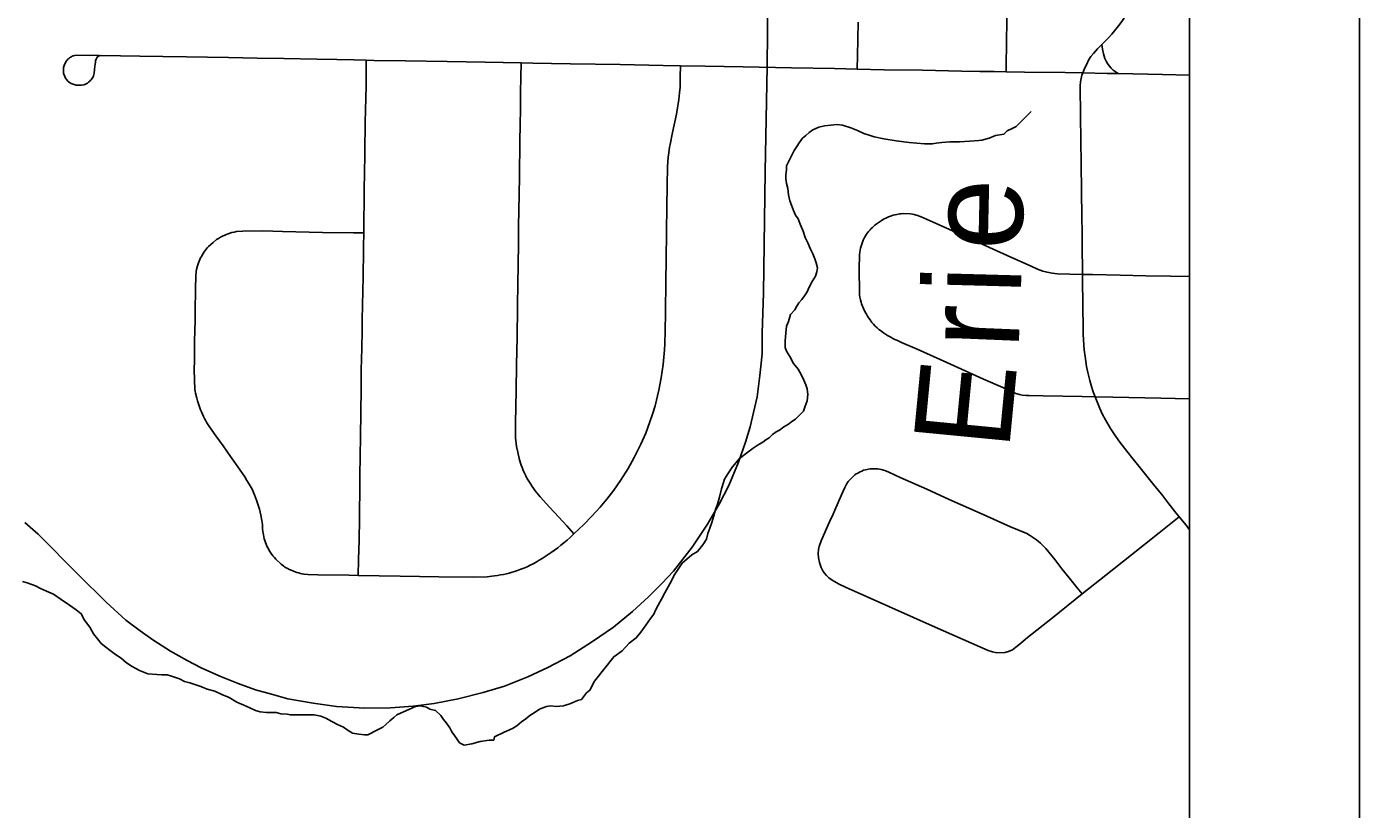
# Model space of a CAD drawing. Extents: x 0 to 34, y 0 to 22.
# Drawn here: x 8.215 to 9, y 16.402 to 16.863 of the extents above; entities that cross this region are included whole.
import ezdxf

# ---------------------------------------------------------------- set-up
doc = ezdxf.new("R2010")
doc.units = 0
for name, color, linetype in [('GM_X_City_Street', 7, 'Continuous'), ('GM_X_County_Text', 7, 'Continuous'), ('GM_X_Minor_River', 7, 'Continuous'), ('GM_X_Rail_Line', 7, 'Continuous'), ('GM_X_Rail_Line_Text', 7, 'Continuous'), ('SH_Cut_Line', 7, 'Continuous'), ('SH_Data', 7, 'Continuous')]:
    doc.layers.add(name, color=color, linetype=linetype)

msp = doc.modelspace()

# ---------------------------------------------------------------- linework, layer by layer
at = {"layer": 'GM_X_City_Street'}
for points in [[(8.8371, 16.83566), (8.83838, 16.83864), (8.8394, 16.84088), (8.84045, 16.84306), (8.84194, 16.84532), (8.84336, 16.84714), (8.84579, 16.8498), (8.84834, 16.85231), (8.85039, 16.85424), (8.85233, 16.85629), (8.85415, 16.85844), (8.85737, 16.86239), (8.85892, 16.86442), (8.86043, 16.86647), (8.86914, 16.8802), (8.87274, 16.88638), (8.87747, 16.8944), (8.88206, 16.90192), (8.88668, 16.90932), (8.89644, 16.92543), (8.9, 16.93126)], [(8.70428, 16.83786), (8.70443, 16.84591), (8.70458, 16.8554), (8.70485, 16.86555)], [(8.79191, 16.83632), (8.79203, 16.84148), (8.7921, 16.85181), (8.79247, 16.86816)], [(8.25768, 16.84593), (8.24458, 16.84607), (8.24336, 16.84591), (8.24256, 16.84568), (8.24196, 16.84548), (8.24141, 16.84519), (8.24087, 16.84487), (8.24036, 16.8445), (8.23987, 16.8441), (8.23941, 16.84367), (8.23899, 16.84322), (8.23859, 16.84272), (8.23823, 16.84221), (8.2379, 16.84167), (8.23737, 16.84059), (8.237, 16.83948), (8.23686, 16.83891), (8.23677, 16.83833), (8.2367, 16.83717), (8.23685, 16.83542), (8.23697, 16.83485), (8.23746, 16.83349), (8.23792, 16.83259), (8.23849, 16.83171), (8.23925, 16.83083), (8.23974, 16.83043), (8.24078, 16.82973), (8.24133, 16.82943), (8.2419, 16.82917), (8.24308, 16.82874), (8.24369, 16.82859), (8.2443, 16.82847), (8.24493, 16.82839), (8.24743, 16.82846), (8.24866, 16.82872), (8.24926, 16.82891), (8.25042, 16.8294), (8.25097, 16.82969), (8.25152, 16.83012), (8.25204, 16.83059), (8.25253, 16.83109), (8.25299, 16.83162), (8.25341, 16.83217), (8.2538, 16.83276), (8.25416, 16.83336), (8.25441, 16.83398), (8.25462, 16.83478), (8.25479, 16.83558), (8.25504, 16.83766), (8.25528, 16.83956), (8.25538, 16.84087), (8.25554, 16.84183), (8.25571, 16.84276), (8.25603, 16.8437), (8.25637, 16.84442), (8.25669, 16.84491), (8.25715, 16.84536), (8.25783, 16.84568), (8.25888, 16.84593), (8.28165, 16.84558), (8.29524, 16.84527), (8.3092, 16.84518), (8.33395, 16.84463), (8.35092, 16.84431), (8.36661, 16.8441), (8.38596, 16.84373), (8.39783, 16.84351), (8.40795, 16.84325), (8.41512, 16.84312), (8.41962, 16.84301), (8.43815, 16.84271), (8.46281, 16.84228), (8.48513, 16.8419), (8.50624, 16.84159), (8.51312, 16.84143), (8.52411, 16.84125), (8.53541, 16.84103), (8.56461, 16.8405), (8.58992, 16.84004), (8.60026, 16.83986), (8.61476, 16.83959), (8.63711, 16.83921), (8.66549, 16.83872), (8.69095, 16.83818), (8.70428, 16.83786), (8.72013, 16.83755), (8.74273, 16.8372), (8.76561, 16.83676), (8.77657, 16.83657), (8.78489, 16.83644), (8.79191, 16.83632), (8.80283, 16.83612), (8.82669, 16.83582), (8.8371, 16.83566), (8.85151, 16.83539), (8.85798, 16.83526), (8.88413, 16.83471), (8.9, 16.83441)], [(8.85798, 16.83526), (8.85505, 16.83735), (8.85379, 16.83851), (8.85264, 16.83975), (8.85164, 16.84113), (8.85079, 16.8426), (8.85011, 16.84415), (8.8497, 16.84548), (8.84934, 16.84683), (8.84876, 16.84955), (8.84834, 16.85231)], [(8.41364, 16.7415), (8.40752, 16.74157), (8.38922, 16.7418), (8.36581, 16.74231), (8.36, 16.74245), (8.3542, 16.74262), (8.34241, 16.74253), (8.33875, 16.74227), (8.33729, 16.74196), (8.33591, 16.74166), (8.33322, 16.74082), (8.33182, 16.74024), (8.33034, 16.73953), (8.32933, 16.73905), (8.32808, 16.73824), (8.32698, 16.73753), (8.32483, 16.73579), (8.32358, 16.73475), (8.32217, 16.73339), (8.32146, 16.73265), (8.32078, 16.73188), (8.32015, 16.73108), (8.31954, 16.73026), (8.31899, 16.7294), (8.31796, 16.72764), (8.31749, 16.72674), (8.31707, 16.72583), (8.3163, 16.72395), (8.31568, 16.72202), (8.31518, 16.72002), (8.31498, 16.71898), (8.31483, 16.71794), (8.31472, 16.7169), (8.31465, 16.71585), (8.31453, 16.70892), (8.31433, 16.69476), (8.31424, 16.69148), (8.31407, 16.68226), (8.314, 16.6796), (8.31383, 16.66521), (8.31376, 16.66237), (8.31388, 16.65388), (8.31404, 16.6505), (8.31418, 16.64939), (8.31435, 16.64827), (8.31458, 16.64707), (8.31524, 16.64431), (8.31571, 16.64258), (8.31623, 16.64085), (8.3168, 16.63914), (8.31742, 16.63745), (8.31797, 16.63611), (8.31855, 16.63479), (8.31918, 16.63348), (8.31984, 16.6322), (8.32053, 16.63093), (8.32127, 16.62969), (8.32204, 16.62846), (8.32284, 16.62726), (8.32648, 16.62213), (8.33079, 16.61609), (8.33517, 16.60995), (8.33798, 16.60582), (8.33941, 16.60386), (8.34081, 16.60187), (8.34218, 16.59986), (8.3435, 16.59783), (8.3448, 16.59577), (8.34605, 16.5937), (8.34728, 16.5916), (8.348, 16.59018), (8.34868, 16.58873), (8.34932, 16.58727), (8.34992, 16.58579), (8.35054, 16.5841), (8.35113, 16.58238), (8.35166, 16.58065), (8.35216, 16.57891), (8.3526, 16.57715), (8.353, 16.57539), (8.35358, 16.57229), (8.35377, 16.57096), (8.3539, 16.56962), (8.35405, 16.56713), (8.35416, 16.56599), (8.3543, 16.56485), (8.35449, 16.56372), (8.35471, 16.56259), (8.35498, 16.56147), (8.35528, 16.56037), (8.35568, 16.55928), (8.35611, 16.55821), (8.35658, 16.55714), (8.3571, 16.5561), (8.35766, 16.55509), (8.35798, 16.55448), (8.35832, 16.55389), (8.35869, 16.55332), (8.35909, 16.55276), (8.36013, 16.55141), (8.36096, 16.55044), (8.36182, 16.54951), (8.36271, 16.54861), (8.3643, 16.54709), (8.36499, 16.54647), (8.36571, 16.54589), (8.36645, 16.54534), (8.36721, 16.54482), (8.368, 16.54434), (8.36881, 16.5439), (8.36963, 16.54348), (8.37047, 16.54311), (8.37231, 16.54237), (8.37329, 16.542), (8.37429, 16.54167), (8.37531, 16.54137), (8.37633, 16.54112), (8.37725, 16.54082), (8.37851, 16.54059), (8.38066, 16.5405), (8.38647, 16.5403), (8.40492, 16.54001), (8.41035, 16.53993), (8.43502, 16.53953), (8.45787, 16.5391), (8.4785, 16.53884), (8.48625, 16.53914), (8.48768, 16.53926), (8.48911, 16.53942), (8.49054, 16.53963), (8.49231, 16.53987), (8.49408, 16.54016), (8.49585, 16.5405), (8.4976, 16.54088), (8.49934, 16.5413), (8.50108, 16.54176), (8.50239, 16.54215), (8.50426, 16.54281), (8.50612, 16.54352), (8.50796, 16.54427), (8.50978, 16.54505), (8.51159, 16.54587), (8.51338, 16.54673), (8.5152, 16.54774), (8.51699, 16.54879), (8.51876, 16.54987), (8.52051, 16.55098), (8.52224, 16.55213), (8.52406, 16.55341), (8.52597, 16.5548), (8.52785, 16.55622), (8.5297, 16.55768), (8.53153, 16.55917), (8.53333, 16.5607), (8.5351, 16.56226), (8.53735, 16.56435), (8.54318, 16.56987), (8.54797, 16.57477), (8.55277, 16.57999), (8.55686, 16.58485), (8.56085, 16.59006), (8.56482, 16.59569), (8.56934, 16.60289), (8.57282, 16.60926), (8.57677, 16.61714), (8.57968, 16.62364), (8.58219, 16.6303), (8.58363, 16.63481), (8.58516, 16.63978), (8.58749, 16.64886), (8.5888, 16.6561), (8.58991, 16.66411), (8.59068, 16.67274), (8.59087, 16.67612), (8.59109, 16.68405), (8.59127, 16.69423), (8.5915, 16.71347), (8.59164, 16.72497), (8.59199, 16.7427), (8.59213, 16.75642), (8.59234, 16.76956), (8.59246, 16.7802), (8.5927, 16.78356), (8.59295, 16.78607), (8.59325, 16.78858), (8.59374, 16.79191), (8.59403, 16.79357), (8.5954, 16.80054), (8.59775, 16.81143), (8.5992, 16.82008), (8.59966, 16.82387), (8.59989, 16.8272), (8.59999, 16.83327), (8.60026, 16.83986)], [(8.41035, 16.53993), (8.41056, 16.54932), (8.41082, 16.56075), (8.41103, 16.57337), (8.41115, 16.58028), (8.41122, 16.58718), (8.4114, 16.59869), (8.41169, 16.62145), (8.41205, 16.6499), (8.41218, 16.66097), (8.41243, 16.67341), (8.41263, 16.68413), (8.41274, 16.69248), (8.41284, 16.69673), (8.41294, 16.70096), (8.41302, 16.70521), (8.4131, 16.70945), (8.41319, 16.71369), (8.41351, 16.73329), (8.41364, 16.7415), (8.41373, 16.7471), (8.41383, 16.76196), (8.41395, 16.76863), (8.4141, 16.77531), (8.41424, 16.78907), (8.41443, 16.8066), (8.41465, 16.81372), (8.41484, 16.82084), (8.41499, 16.82795), (8.41506, 16.83552), (8.41512, 16.84312)], [(8.53735, 16.56435), (8.5333, 16.56902), (8.5286, 16.57416), (8.52303, 16.58003), (8.51761, 16.58606), (8.51657, 16.58724), (8.51558, 16.58843), (8.51462, 16.58967), (8.5137, 16.59093), (8.51282, 16.59222), (8.51198, 16.59354), (8.51118, 16.59487), (8.51045, 16.59603), (8.50975, 16.59722), (8.50909, 16.59843), (8.50847, 16.59965), (8.50789, 16.60089), (8.50734, 16.60215), (8.50683, 16.60343), (8.50636, 16.60472), (8.50593, 16.60603), (8.50555, 16.60734), (8.50519, 16.60867), (8.50427, 16.61244), (8.50356, 16.61581), (8.50335, 16.61748), (8.50318, 16.61915), (8.50305, 16.62083), (8.50297, 16.6225), (8.50308, 16.63095), (8.50318, 16.6377), (8.50353, 16.66238), (8.50381, 16.67318), (8.50389, 16.67858), (8.50415, 16.6992), (8.50433, 16.7109), (8.50469, 16.73485), (8.50484, 16.74541), (8.50512, 16.76399), (8.50528, 16.77493), (8.50559, 16.79545), (8.50576, 16.80499), (8.5059, 16.81453), (8.50602, 16.82407), (8.50617, 16.83306), (8.50624, 16.84159)], [(8.9, 16.56679), (8.89791, 16.5694), (8.89378, 16.57441), (8.89136, 16.57759), (8.88716, 16.58287), (8.88358, 16.58746), (8.87945, 16.59248), (8.87484, 16.59836), (8.87013, 16.60416), (8.86682, 16.60835), (8.86297, 16.61306), (8.85897, 16.6183), (8.8565, 16.62167), (8.85351, 16.62637), (8.85051, 16.63138), (8.84879, 16.6347), (8.84707, 16.63823), (8.84437, 16.64499), (8.8432, 16.64801), (8.84223, 16.65101), (8.84122, 16.6546), (8.84004, 16.65938), (8.8393, 16.66291), (8.83845, 16.66868), (8.83794, 16.67274), (8.83764, 16.67559), (8.83737, 16.68165), (8.83711, 16.7022), (8.83703, 16.71078), (8.83698, 16.71708), (8.83672, 16.73517), (8.83666, 16.74183), (8.83649, 16.75047), (8.8361, 16.78208), (8.83598, 16.79586), (8.83584, 16.81043), (8.83564, 16.82808), (8.83578, 16.83038), (8.8361, 16.83233), (8.83656, 16.83427), (8.8371, 16.83566)], [(8.70544, 16.72015), (8.70556, 16.72851), (8.70573, 16.73013), (8.70593, 16.73134), (8.70619, 16.73255), (8.70652, 16.73375), (8.70689, 16.73493), (8.70732, 16.73608), (8.70781, 16.73722), (8.70855, 16.73869), (8.70916, 16.73976), (8.70981, 16.74079), (8.71038, 16.74158), (8.71098, 16.74236), (8.71184, 16.74335), (8.71252, 16.74406), (8.71322, 16.74475), (8.71396, 16.7454), (8.71472, 16.74602), (8.71551, 16.74661), (8.71659, 16.74734), (8.71828, 16.74849), (8.71918, 16.7491), (8.72011, 16.74967), (8.72107, 16.75018), (8.72273, 16.75095), (8.72444, 16.75157), (8.72549, 16.75187), (8.72654, 16.75212), (8.72926, 16.75261), (8.73015, 16.75272), (8.73149, 16.75282), (8.73554, 16.75268), (8.73688, 16.75247), (8.73776, 16.75229), (8.73907, 16.75195), (8.73992, 16.75169), (8.74077, 16.7514), (8.742, 16.75089), (8.75253, 16.74618), (8.77178, 16.73751), (8.79467, 16.72719), (8.80664, 16.7219), (8.81047, 16.72013), (8.81363, 16.71902), (8.81609, 16.71834), (8.81907, 16.71775), (8.82226, 16.71746), (8.82943, 16.71728), (8.83698, 16.71708), (8.84287, 16.717), (8.85909, 16.71666), (8.87426, 16.71628), (8.88882, 16.71609), (8.9, 16.71581)], [(8.70544, 16.72015), (8.70551, 16.70651), (8.70565, 16.70505), (8.70586, 16.70359), (8.70615, 16.70215), (8.70653, 16.70072), (8.70687, 16.69967), (8.70739, 16.69829), (8.70797, 16.69695), (8.70903, 16.69478), (8.70966, 16.6936), (8.71033, 16.69245), (8.71105, 16.69133), (8.71182, 16.69023), (8.71292, 16.68882), (8.71379, 16.68781), (8.7147, 16.68683), (8.71597, 16.6856), (8.71697, 16.68472), (8.71789, 16.684), (8.71981, 16.68259), (8.72092, 16.68185), (8.72206, 16.68114), (8.72399, 16.68003), (8.72518, 16.67941), (8.72638, 16.67883), (8.7276, 16.67828), (8.73034, 16.67707), (8.73951, 16.67303), (8.75696, 16.66516), (8.77873, 16.65547), (8.78999, 16.65045), (8.7976, 16.64702), (8.79976, 16.64632), (8.80147, 16.64605), (8.80375, 16.64577), (8.80559, 16.6457), (8.81376, 16.64559), (8.83671, 16.64513), (8.84437, 16.64499)], [(8.84437, 16.64499), (8.85485, 16.64486), (8.88306, 16.64428), (8.9, 16.64391)], [(8.83674, 16.52898), (8.83387, 16.53256), (8.82914, 16.53844), (8.82483, 16.54388), (8.82061, 16.54922), (8.81888, 16.55138), (8.81533, 16.55578), (8.81217, 16.55889), (8.80984, 16.56086), (8.8081, 16.56209), (8.80579, 16.56363), (8.80414, 16.56449), (8.79463, 16.56859), (8.77663, 16.57664), (8.75841, 16.58468), (8.74519, 16.59063), (8.72947, 16.59762), (8.7228, 16.60062), (8.72055, 16.60156), (8.71834, 16.60222), (8.71633, 16.60261), (8.71398, 16.60271), (8.7118, 16.60261), (8.70914, 16.60212), (8.70803, 16.60178), (8.70734, 16.60152), (8.70552, 16.60066), (8.70458, 16.60014), (8.70371, 16.59963), (8.70285, 16.59902), (8.70194, 16.59822), (8.70021, 16.59656), (8.69901, 16.59512), (8.698, 16.59356), (8.69696, 16.59173), (8.69605, 16.58946), (8.69501, 16.58725), (8.69101, 16.57833), (8.69002, 16.57598), (8.68797, 16.57153), (8.68297, 16.56026), (8.68176, 16.55691), (8.6814, 16.55512), (8.68121, 16.55287), (8.6814, 16.55021), (8.68199, 16.54747), (8.68305, 16.54463), (8.68403, 16.54261), (8.68484, 16.54145), (8.68623, 16.53989), (8.68751, 16.5385), (8.68942, 16.53705), (8.69324, 16.53492), (8.69775, 16.53289), (8.71019, 16.52739), (8.75023, 16.50951), (8.78142, 16.49563), (8.7839, 16.49493), (8.78639, 16.49442), (8.79125, 16.49459), (8.79344, 16.49522), (8.79571, 16.4962), (8.79767, 16.49765), (8.79947, 16.49898), (8.80462, 16.50344), (8.81919, 16.5149), (8.83674, 16.52898), (8.85062, 16.53999), (8.86587, 16.55207), (8.88203, 16.56501), (8.89378, 16.57441)]]:
    msp.add_lwpolyline(points, dxfattribs=at)
at = {"layer": 'GM_X_County_Text'}
msp.add_lwpolyline([(6.61711, 15.32914), (8.9, 15.30473), (8.9, 20.9), (2.1, 20.9)], dxfattribs=at)
at = {"layer": 'GM_X_Minor_River'}
for points in [[(8.64592, 16.61674), (8.64858, 16.61826), (8.65048, 16.61978), (8.65238, 16.62092), (8.65428, 16.62282), (8.65656, 16.62434), (8.65846, 16.62548), (8.66112, 16.62738), (8.66378, 16.6289), (8.66568, 16.63042), (8.66796, 16.63194), (8.67252, 16.63651), (8.67365, 16.63955), (8.67479, 16.64259), (8.67517, 16.64639), (8.67479, 16.64981), (8.67403, 16.65209), (8.67289, 16.65475), (8.67137, 16.65779), (8.66946, 16.66121), (8.6668, 16.66462), (8.66452, 16.6688), (8.66262, 16.67184), (8.66185, 16.67412), (8.66185, 16.67792), (8.66223, 16.68248), (8.66261, 16.68666), (8.66375, 16.68932), (8.66489, 16.6935), (8.66755, 16.69616), (8.66869, 16.69844), (8.66983, 16.70034), (8.67173, 16.70225), (8.67325, 16.70453), (8.67477, 16.70681), (8.6759, 16.70947), (8.6778, 16.71289), (8.6797, 16.71593), (8.68046, 16.71859), (8.68084, 16.72087), (8.68008, 16.72391), (8.67932, 16.72619), (8.67818, 16.72923), (8.67665, 16.73189), (8.67513, 16.73568), (8.67361, 16.73873), (8.67247, 16.74252), (8.67057, 16.7467), (8.66942, 16.74974), (8.6679, 16.75202), (8.66676, 16.75468), (8.66562, 16.75772), (8.66448, 16.76038), (8.66372, 16.7638), (8.66333, 16.7676), (8.66257, 16.77064), (8.66219, 16.7733), (8.66219, 16.77558), (8.66257, 16.77862), (8.66257, 16.7809), (8.66713, 16.79002), (8.66864, 16.7923), (8.67016, 16.79458), (8.67206, 16.79724), (8.67396, 16.79876), (8.67586, 16.80066), (8.67814, 16.80218), (8.68156, 16.80371), (8.68498, 16.80447), (8.68878, 16.80485), (8.69221, 16.80523), (8.69563, 16.80486), (8.70057, 16.80334), (8.70437, 16.80182), (8.70817, 16.79992), (8.71197, 16.79878), (8.71425, 16.79802), (8.71995, 16.79689), (8.72718, 16.79575), (8.73478, 16.79461), (8.7439, 16.79386), (8.74846, 16.79386), (8.75074, 16.79424), (8.75416, 16.79462), (8.75872, 16.795), (8.76443, 16.79501), (8.77051, 16.79539), (8.77583, 16.79577), (8.77773, 16.79615), (8.78191, 16.79729), (8.78571, 16.79882), (8.79065, 16.79958), (8.79255, 16.80148), (8.79559, 16.803), (8.79787, 16.80414), (8.80053, 16.8068), (8.80395, 16.81022), (8.80672, 16.813)], [(8.36016, 16.45929), (8.36206, 16.45929), (8.36472, 16.45854), (8.36852, 16.45816), (8.37042, 16.45778), (8.3727, 16.45778), (8.37612, 16.45778), (8.38182, 16.45778), (8.38448, 16.45779), (8.38829, 16.45703), (8.39133, 16.45589), (8.39475, 16.45399), (8.39817, 16.45209), (8.40159, 16.45057), (8.40387, 16.44905), (8.40692, 16.44715), (8.41072, 16.4464), (8.41414, 16.44602), (8.41604, 16.44602), (8.42174, 16.44906), (8.42478, 16.45058), (8.42668, 16.4521), (8.42896, 16.45438), (8.43124, 16.45629), (8.43314, 16.45781), (8.44226, 16.46199), (8.44416, 16.46275), (8.44682, 16.46313), (8.44872, 16.46275), (8.45062, 16.46237), (8.45252, 16.46124), (8.45594, 16.46048), (8.45898, 16.45744), (8.4605, 16.45516), (8.46241, 16.45288), (8.46431, 16.45022), (8.46545, 16.44794), (8.46697, 16.44566), (8.46849, 16.44376), (8.47001, 16.44148), (8.47268, 16.43996), (8.47724, 16.44072), (8.48218, 16.44225), (8.4875, 16.44301), (8.49016, 16.44301), (8.49054, 16.44491), (8.49624, 16.44758), (8.50118, 16.44986), (8.50384, 16.45138), (8.5065, 16.45366), (8.50916, 16.45556), (8.51144, 16.45746), (8.51448, 16.45936), (8.51714, 16.46126), (8.51904, 16.46202), (8.52132, 16.46279), (8.5236, 16.46316), (8.52702, 16.46279), (8.5312, 16.46317), (8.535, 16.46431), (8.53956, 16.46621), (8.54184, 16.46697), (8.54488, 16.47078), (8.54678, 16.4723), (8.54944, 16.47762), (8.56083, 16.49206), (8.56577, 16.49548), (8.56995, 16.50004), (8.57413, 16.50309), (8.57679, 16.50651), (8.57983, 16.51069), (8.58249, 16.51449), (8.58439, 16.51715), (8.58553, 16.51943), (8.58705, 16.52247), (8.58895, 16.52589), (8.59085, 16.52969), (8.59388, 16.53501), (8.59692, 16.54072), (8.6011, 16.54718), (8.6068, 16.55212), (8.61022, 16.55402), (8.61326, 16.55782), (8.61554, 16.56124), (8.61629, 16.56466), (8.61743, 16.56771), (8.61857, 16.57113), (8.61971, 16.57493), (8.62085, 16.57873), (8.62199, 16.58177), (8.62313, 16.58595), (8.62426, 16.59089), (8.6254, 16.59469), (8.62616, 16.59659), (8.62806, 16.59963), (8.6292, 16.60153), (8.63072, 16.60381), (8.6349, 16.60875), (8.63908, 16.61179), (8.64288, 16.61483), (8.64592, 16.61674)], [(8.21264, 16.53637), (8.2153, 16.53561), (8.21758, 16.53485), (8.22025, 16.53371), (8.22329, 16.53219), (8.22671, 16.53068), (8.23089, 16.52878), (8.23545, 16.52574), (8.2404, 16.52232), (8.2442, 16.51966), (8.24724, 16.51739), (8.24914, 16.51358), (8.25219, 16.50941), (8.25447, 16.50561), (8.25675, 16.50257), (8.25903, 16.49991), (8.26169, 16.49763), (8.26435, 16.49573), (8.2674, 16.49345), (8.27082, 16.49118), (8.27386, 16.48852), (8.27728, 16.48624), (8.28146, 16.48396), (8.28641, 16.48206), (8.29173, 16.48168), (8.29477, 16.48131), (8.29781, 16.48131), (8.30047, 16.48055), (8.30275, 16.47979), (8.30503, 16.47903), (8.30807, 16.47751), (8.31112, 16.47675), (8.31758, 16.47447), (8.32138, 16.47296), (8.32594, 16.47182), (8.33012, 16.46992), (8.33431, 16.46802), (8.33887, 16.46536), (8.34305, 16.46347), (8.34647, 16.46195), (8.34989, 16.46043), (8.35255, 16.45967), (8.35635, 16.45929), (8.36016, 16.45929)]]:
    msp.add_lwpolyline(points, dxfattribs=at)
at = {"layer": 'GM_X_Rail_Line'}
msp.add_lwpolyline([(8.21405, 16.57102), (8.22176, 16.56411), (8.24568, 16.5403), (8.2619, 16.52408), (8.27357, 16.51354), (8.28185, 16.5073), (8.28945, 16.50197), (8.29976, 16.49528), (8.30951, 16.48984), (8.31779, 16.48553), (8.32879, 16.48054), (8.33956, 16.47624), (8.34976, 16.47261), (8.35929, 16.47011), (8.36893, 16.46728), (8.38389, 16.46467), (8.39761, 16.46286), (8.41417, 16.46184), (8.42936, 16.46195), (8.44262, 16.46297), (8.4551, 16.46456), (8.46915, 16.46728), (8.48389, 16.47091), (8.49648, 16.47465), (8.5102, 16.4802), (8.5221, 16.48565), (8.53526, 16.49256), (8.54841, 16.50095), (8.56065, 16.50946), (8.57199, 16.51875), (8.5814, 16.52726), (8.58911, 16.53519), (8.59603, 16.54245), (8.60703, 16.55651), (8.6161, 16.57), (8.62301, 16.58179), (8.62868, 16.5929), (8.63435, 16.60662), (8.63855, 16.61841), (8.64115, 16.62726), (8.64319, 16.63588), (8.64523, 16.64506), (8.64694, 16.65753), (8.64818, 16.67023), (8.6483, 16.6827), (8.64898, 16.70594), (8.65011, 16.77771), (8.65113, 16.83939), (8.65215, 16.93996)], dxfattribs=at)
at = {"layer": 'SH_Cut_Line'}
msp.add_lwpolyline([(6.61711, 15.32914), (8.9, 15.30473), (8.9, 20.9), (2.1, 20.9)], dxfattribs=at)
at = {"layer": 'SH_Data'}
for p, q in [((9, 21), (9, 14)), ((8.9, 20.9), (8.9, 14.1))]:
    msp.add_line(p, q, dxfattribs=at)

# ---------------------------------------------------------------- texts
at = {"layer": 'GM_X_Rail_Line_Text'}
for s, rotation, p in [('e', 88.72555, (8.80132, 16.73084)), ('i', 88.44588, (8.80061, 16.70472)), ('r', 87.63187, (8.79929, 16.67271)), ('E', 84.48865, (8.79361, 16.61287))]:
    msp.add_text(s, height=0.05663, rotation=rotation, dxfattribs=at).set_placement(p)

doc.saveas('drawing.dxf')
